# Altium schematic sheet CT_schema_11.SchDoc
size 388 x 278 mm
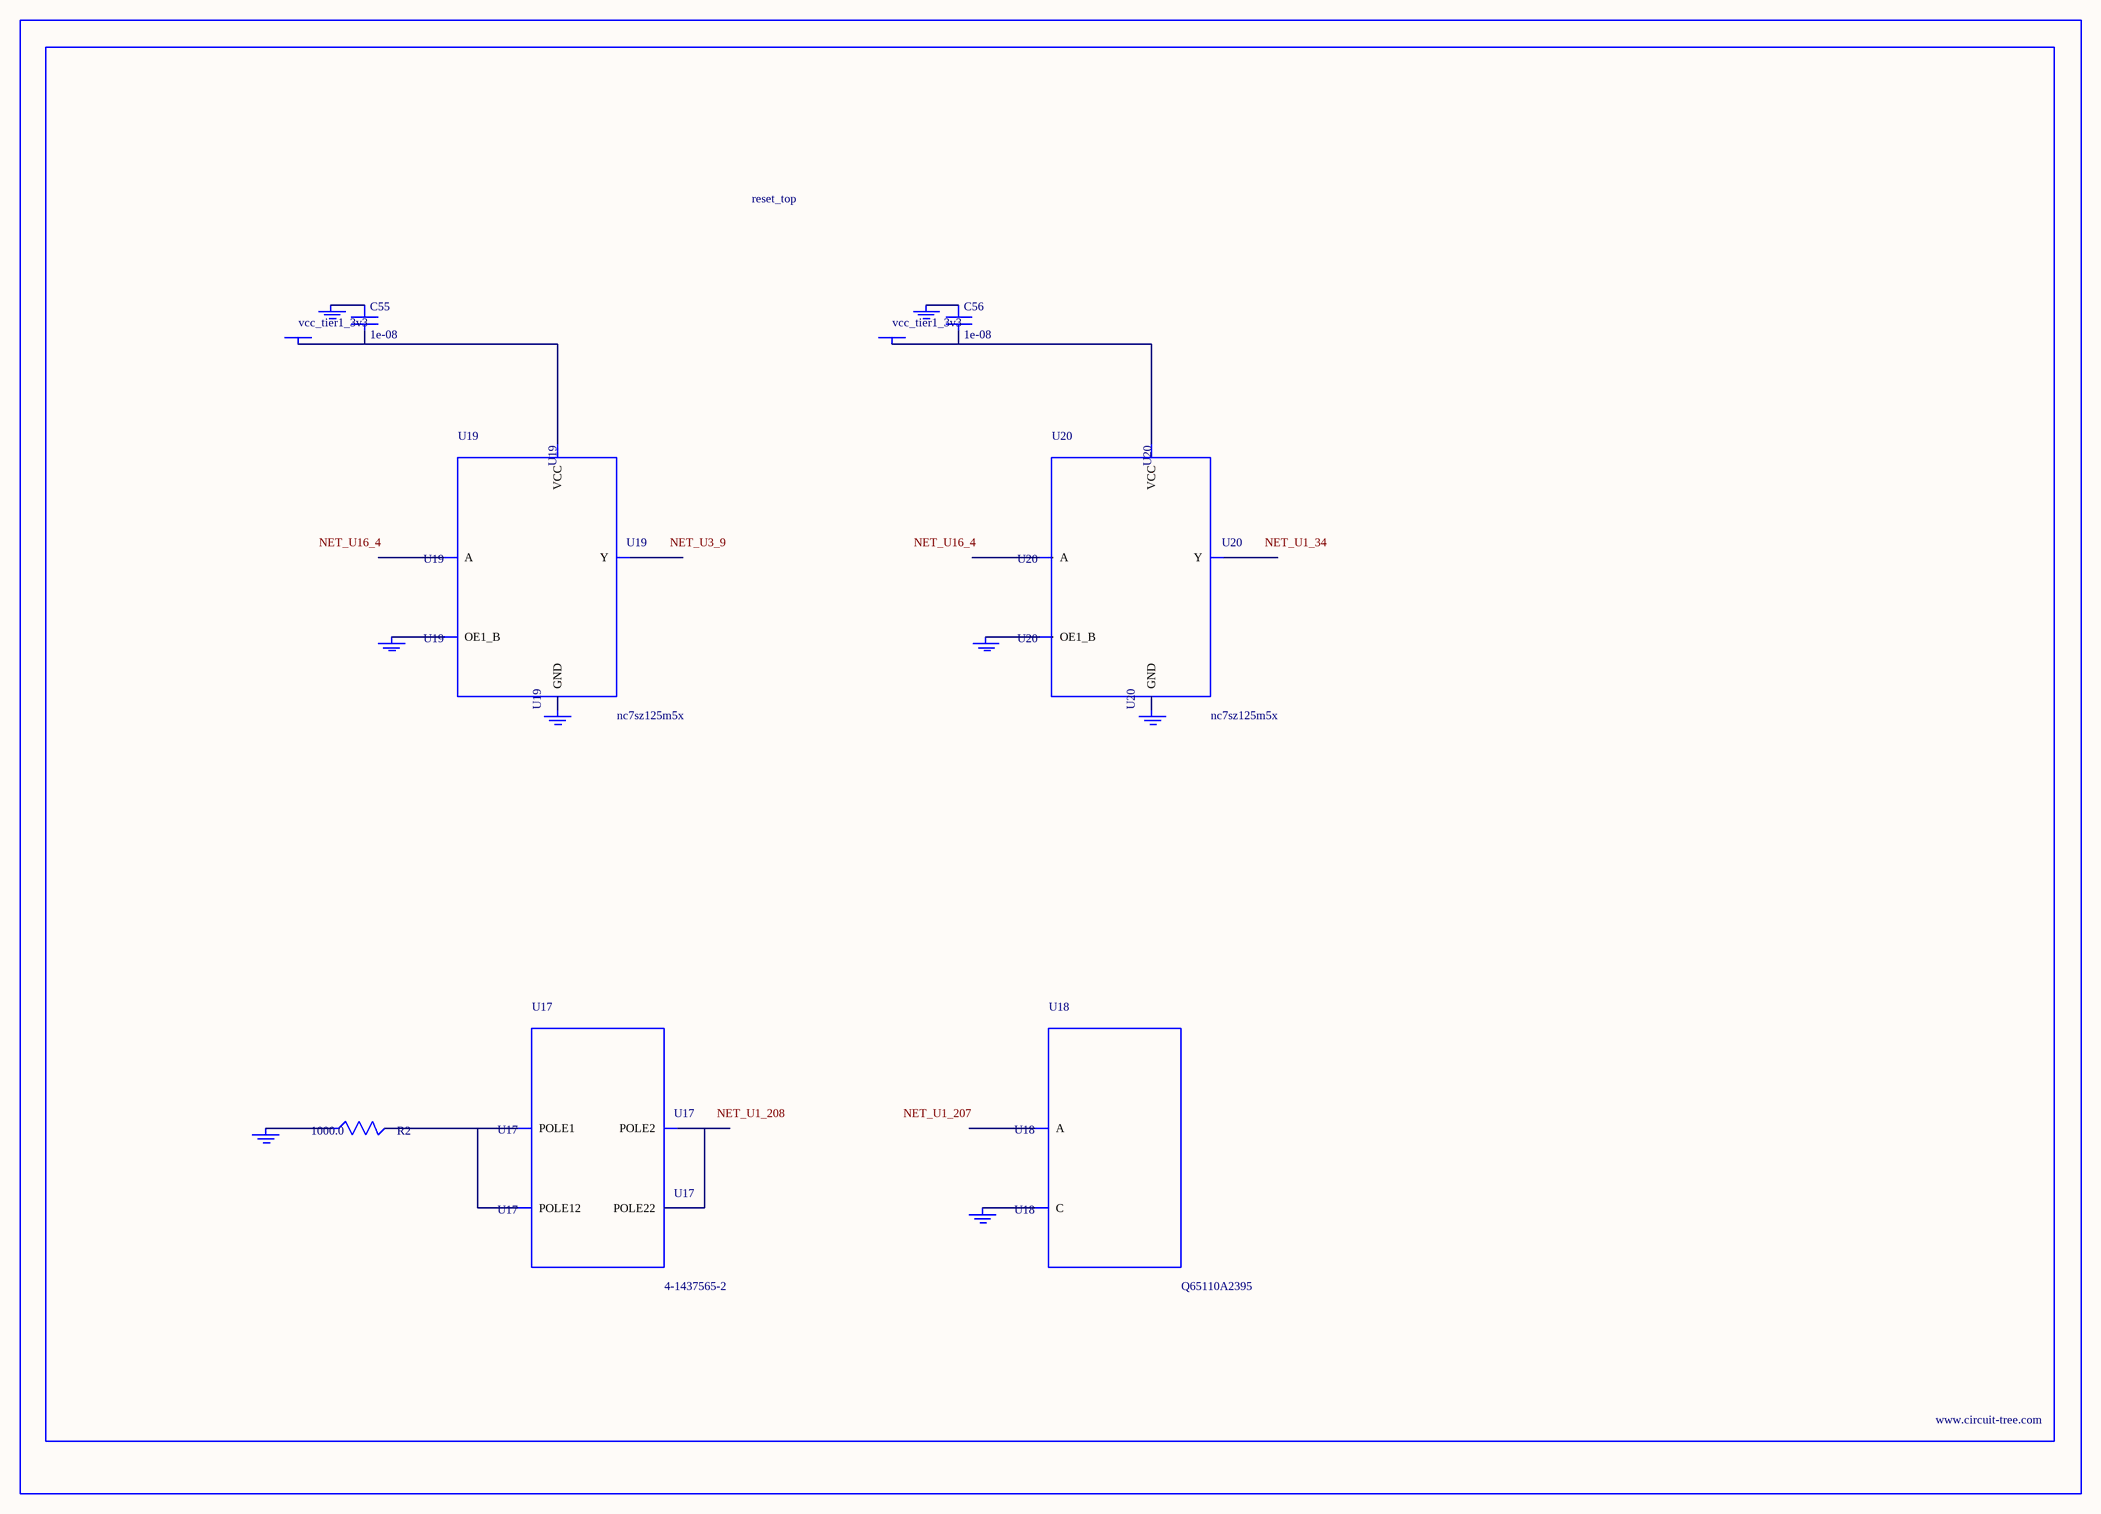
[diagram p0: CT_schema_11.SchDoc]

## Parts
BORDER10  (no value)
C55  1e-08  [C0402]
C56  1e-08  [C0402]
GND_INSTANCE_10_0  (no value)
GND_INSTANCE_10_1  (no value)
GND_INSTANCE_10_2  (no value)
GND_INSTANCE_10_3  (no value)
GND_INSTANCE_10_4  (no value)
GND_INSTANCE_10_5  (no value)
GND_INSTANCE_10_6  (no value)
GND_INSTANCE_10_7  (no value)
POWER_INSTANCE_10_0  vcc_tier1_3v3
POWER_INSTANCE_10_1  vcc_tier1_3v3
R2  1000.0  [R0603]
U17  4-1437565-2  [SW_4-1437565-2]
U18  Q65110A2395  [LGM67K-G1J2-24-Z]
U19  nc7sz125m5x  [NC7SZ125M5X]
U20  nc7sz125m5x  [NC7SZ125M5X]

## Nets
NetC55_1: C55.1 GND_INSTANCE_10_2.0(GND)
NetC55_2: C55.2 POWER_INSTANCE_10_0.0(PWR) U19.5(VCC)
NetC56_1: C56.1 GND_INSTANCE_10_5.0(GND)
NetC56_2: C56.2 POWER_INSTANCE_10_1.0(PWR) U20.5(VCC)
NetGND_INSTANCE_10_0_0: GND_INSTANCE_10_0.0(GND) R2.1
NetGND_INSTANCE_10_1_0: GND_INSTANCE_10_1.0(GND) U18.C
NetGND_INSTANCE_10_3_0: GND_INSTANCE_10_3.0(GND) U19.1(OE1_B)
NetGND_INSTANCE_10_4_0: GND_INSTANCE_10_4.0(GND) U19.3(GND)
NetGND_INSTANCE_10_6_0: GND_INSTANCE_10_6.0(GND) U20.1(OE1_B)
NetGND_INSTANCE_10_7_0: GND_INSTANCE_10_7.0(GND) U20.3(GND)
NetR2_2: R2.2 U17.1(POLE1) U17.2(POLE12)
NetU17_3: U17.3(POLE2) U17.4(POLE22)

Not connected (* = marked no-connect by the designer): U18 A; U19 2(A) 4(Y); U20 2(A) 4(Y)

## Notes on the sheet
- Labels drawn without touching a wire or pin: NET_U1_34, NET_U1_207, NET_U1_208, NET_U3_9, NET_U16_4

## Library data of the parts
BORDER10 = BORDER_PAGE10
C55 C56 = C0402C103K3RAC
GND_INSTANCE_10_0-GND_INSTANCE_10_7 = GND
POWER_INSTANCE_10_0 POWER_INSTANCE_10_1 = PWR
R2 = RC0603JR-071KL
